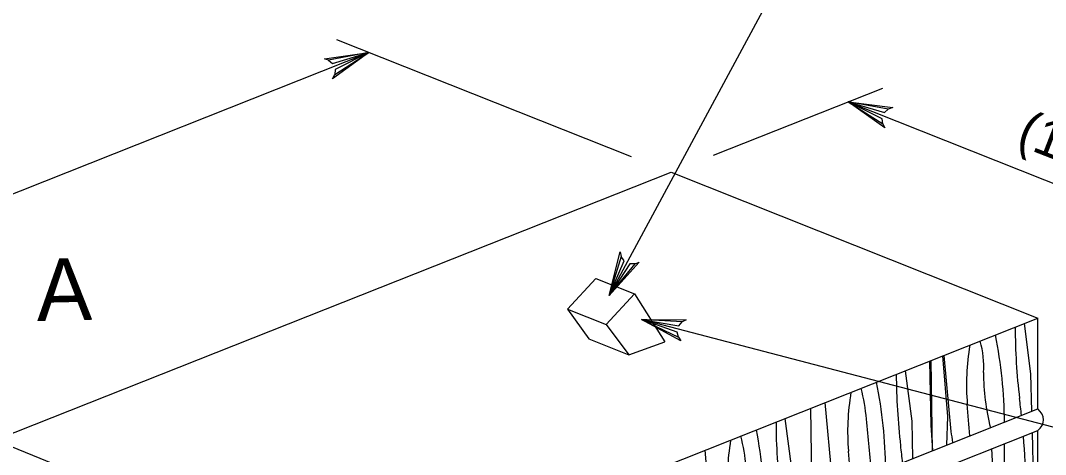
# Model space of a CAD drawing. Extents: x 636462 to 637367, y 299944 to 300538.
# Drawn here: x 636640.4 to 636723, y 300105 to 300139.9 of the extents above; entities that cross this region are included whole.
import ezdxf

# ---------------------------------------------------------------- set-up
doc = ezdxf.new("R2010")
doc.units = 0
doc.layers.add('Default', color=7, linetype='Continuous')

# ---------------------------------------------------------------- blocks, each defined once
blk = doc.blocks.new('CC')
at = {"layer": 'Default'}
for p, q in [((-0.01466, 0.03378), (-0.02861, 0.01185)), ((-0.01466, 0.03378), (0.00435, 0.02272)), ((0.00435, 0.02272), (-0.00959, 0.00079)), ((0.00435, 0.02272), (0.01928, -0.01161)), ((-0.02861, 0.01185), (-0.01815, -0.00936)), ((-0.02861, 0.01185), (-0.00959, 0.00079)), ((-0.00959, 0.00079), (0.00149, -0.02101)), ((-0.01815, -0.00936), (0.00149, -0.02101)), ((0.00149, -0.02101), (0.01928, -0.01161))]:
    blk.add_line(p, q, dxfattribs=at)

msp = doc.modelspace()

# ---------------------------------------------------------------- linework, layer by layer
at = {"layer": 'Default'}
for p, q in [((636689.648, 300128.944), (636665.92, 300138.353)), ((636590.304, 300106.329), (636668.489, 300137.334)), ((636696.251, 300129.064), (636709.899, 300134.477)), ((636707.118, 300133.374), (636736.655, 300121.596)), ((636614.653, 300096.705), (636692.838, 300127.711)), ((636692.838, 300127.711), (636722.375, 300115.933)), ((636644.271, 300084.96), (636722.375, 300115.933)), ((636721.829, 300111.452), (636721.302, 300115.507)), ((636722.375, 300108.625), (636722.375, 300115.933)), ((636715.125, 300108.01), (636714.743, 300112.907)), ((636715.399, 300106.82), (636714.844, 300112.947)), ((636713.8, 300107.319), (636713.674, 300112.483)), ((636713.891, 300105.261), (636713.785, 300112.526)), ((636625.772, 300111.279), (636734.467, 300066.973)), ((636712.251, 300107.654), (636711.724, 300111.709)), ((636721.908, 300108.44), (636721.829, 300111.452)), ((636705.821, 300103.022), (636705.267, 300109.148)), ((636691.995, 300096.577), (636722.375, 300108.625)), ((636704.203, 300101.419), (636704.097, 300108.684)), ((636715.048, 300105.72), (636715.125, 300108.01)), ((636702.563, 300103.812), (636702.036, 300107.867)), ((636712.33, 300104.642), (636712.251, 300107.654)), ((636713.94, 300105.28), (636713.8, 300107.319)), ((636692.04, 300094.864), (636722.375, 300106.894)), ((636722.133, 300099.849), (636721.953, 300106.727)), ((636722.375, 300094.53), (636722.375, 300106.894)), ((636696.133, 300099.18), (636695.578, 300105.306))]:
    msp.add_line(p, q, dxfattribs=at)
for points in [[(636708.171, 300147.169), (636703.704, 300147.169), (636687.863, 300117.773)], [(636665.25, 300136.736), (636664.917, 300136.845), (636668.489, 300137.334), (636665.25, 300136.736), (636665.57, 300136.462), (636668.489, 300137.334), (636665.768, 300135.977), (636665.737, 300135.561), (636668.489, 300137.334), (636665.568, 300135.221), (636665.737, 300135.561)], [(636709.889, 300131.592), (636710.057, 300131.285), (636707.118, 300133.374), (636709.889, 300131.592), (636709.844, 300132.011), (636707.118, 300133.374), (636710.031, 300132.5), (636710.338, 300132.782), (636707.118, 300133.374), (636710.694, 300132.914), (636710.338, 300132.782)], [(636689.95, 300120.322), (636690.274, 300120.454), (636687.863, 300117.773), (636689.95, 300120.322), (636689.528, 300120.325), (636687.863, 300117.773), (636689.064, 300120.567), (636688.819, 300120.904), (636687.863, 300117.773), (636688.729, 300121.273), (636688.819, 300120.904)], [(636741.914, 300105.074), (636731.615, 300105.074), (636690.459, 300115.838)], [(636693.426, 300114.406), (636693.63, 300114.122), (636690.459, 300115.838), (636693.426, 300114.406), (636693.33, 300114.817), (636690.459, 300115.838), (636693.456, 300115.325), (636693.727, 300115.642), (636690.459, 300115.838), (636694.065, 300115.816), (636693.727, 300115.642)]]:
    msp.add_lwpolyline(points, dxfattribs=at)
for centre, major_axis, start_param, end_param in [((636638.536, 300107.118), (-81.173, 0), 3.149651, 3.275942), ((636820.536, 300115.215), (-99.972, 0), 6.283185, 6.366999), ((636756.918, 300110.593), (-40.277, 0), 6.168273, 6.340258), ((636703.802, 300112.096), (-14.231, 0), 3.086534, 3.347249), ((636810.958, 300111.417), (99.972, 0), 3.141593, 3.225406), ((636756.645, 300111.572), (38.633, 0), 3.142111, 3.310445), ((636628.958, 300103.319), (-81.173, 0), 3.149651, 3.275942), ((636747.341, 300106.795), (40.277, 0), 3.026681, 3.198665), ((636670.63, 300105.987), (-38.046, 0), 3.211407, 3.307155), ((636358.936, 300094.974), (358.355, 0), 0.046656, 0.057073), ((636545.598, 300099.35), (-175.935, 0), 3.214128, 3.225406), ((636720.931, 300107.76), (1.916, 0), 5.565747, 7.000624), ((636801.27, 300107.575), (-99.972, 0), 6.283185, 6.366999), ((636334.774, 300089.856), (374.723, 0), 0.052314, 0.069814), ((636660.942, 300102.145), (-38.046, 0), 3.211407, 3.307155), ((636619.27, 300099.477), (81.173, 0), 0.008058, 0.134349), ((636574.733, 300095.719), (141.592, 0), 0.105046, 0.114395), ((636545.598, 300099.35), (175.935, 0), 6.273481, 6.341891), ((636737.652, 300102.952), (-40.277, 0), 6.168273, 6.340258), ((636536.02, 300095.551), (-175.935, 0), 3.214128, 3.225406), ((636344.351, 300093.654), (374.723, 0), 0.01472, 0.045767), ((637128.413, 300101.104), (408.782, 0), 3.124763, 3.159463), ((636349.358, 300091.176), (358.355, 0), 0.046656, 0.057073)]:
    msp.add_ellipse(centre, major_axis=major_axis, ratio=0.686868, start_param=start_param, end_param=end_param, dxfattribs=at)

# ---------------------------------------------------------------- block references
at = {"layer": 'Default', "xscale": 163.65853193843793, "yscale": 112.41186802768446}
msp.add_blockref('CC', (636689.182, 300115.34), dxfattribs=at)

# ---------------------------------------------------------------- texts
at = {"layer": 'Default'}
for s, height, rotation, p in [('(18")', 2.998, 338.77426, (636720.563, 300129.941)), ('A', 4.997, 1.26463, (636641.765, 300115.712))]:
    msp.add_text(s, height=height, rotation=rotation, dxfattribs=at).set_placement(p)

doc.saveas('drawing.dxf')
